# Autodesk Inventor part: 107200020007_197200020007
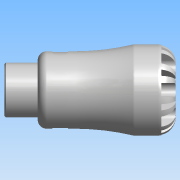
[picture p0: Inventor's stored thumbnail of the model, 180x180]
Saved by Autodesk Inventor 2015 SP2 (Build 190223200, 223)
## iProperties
Created: 2016-12
Part Number: 107200020007_197200020007
Material: PVC-Piping
Description: PLASSON MALE INTEGRAL BRASS THREAD 20X3/4" SERIES 1
Document SubType Name: Modeling
Designer: KIM
Mass: 61.7504 g
Surface Area: 140.097 cm^2
Volume: 44.1074 cm^3
Density: 1.4 g/cm^3
Appearance: Smooth - White
Author: KIM
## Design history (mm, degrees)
derived "1072.ipt"
feature "Solid1::1072.ipt"
tag "TaggingFeature1"
body "Solid1"
other parameters: "d0" = 77, "d1" = 18.9, "d3" = 25, "d4" = 41, "d6" = 45, "d8" = 34.85, "d13" = 6.4, "d14" = 6.4, "d15" = 0, "d17" = 360 deg, "d19" = 8 deg, "d20" = 0.4, "d21" = 0.4, "d22" = 8 deg, "d24" = 0, "d26" = 360 deg, "d32" = 4.1, "d33" = 4.1, "d34" = 24.658, "d38" = 15, "d39" = 0.73974, "d42" = 7, "d43" = 4.6, "d45" = 12.544, "d46" = 0, "d59" = 360 deg, "d61" = 5.95, "d62" = 0.4, "d64" = 0, "d65" = 0.41, "d68" = 2.85714, "E_" = 41, "H_" = 77, "l_" = 45, "R_" = 24.658, "l_2" = 15, "d9" = 8, "d11" = 41, "d12" = 25
